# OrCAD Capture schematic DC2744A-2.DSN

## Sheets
1 PAGE2: size Custom; company: ANALOG DEVICES; note: DEMO BOARD BILL OF MATERIALS; note: HIGH OUTPUT VOLTAGE BOOST CONVERTER
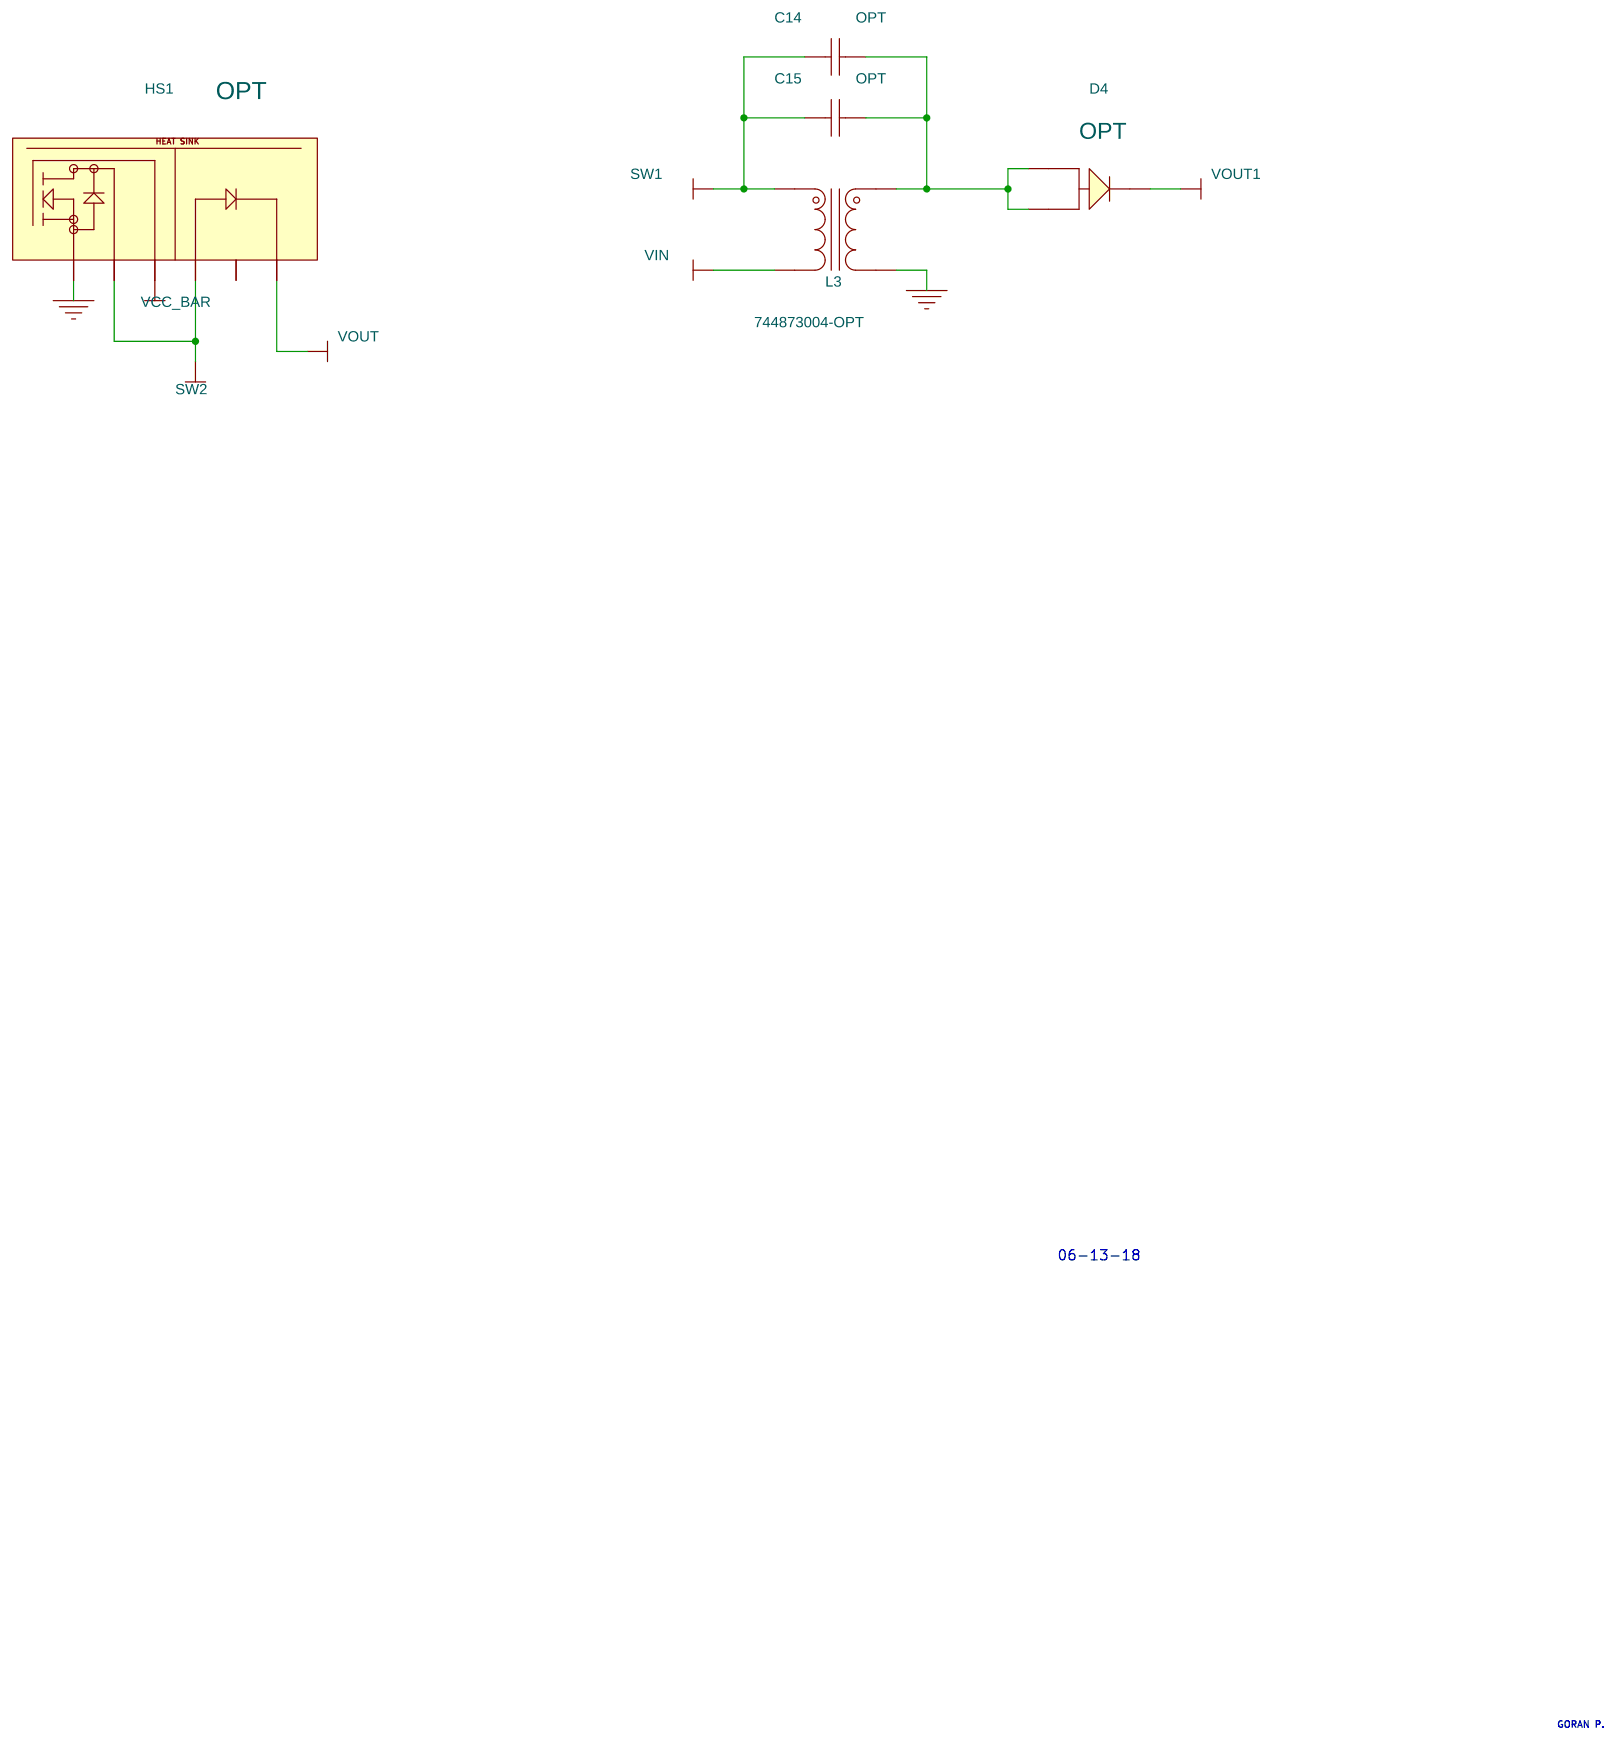
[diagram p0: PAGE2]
2 PAGE1: size Custom
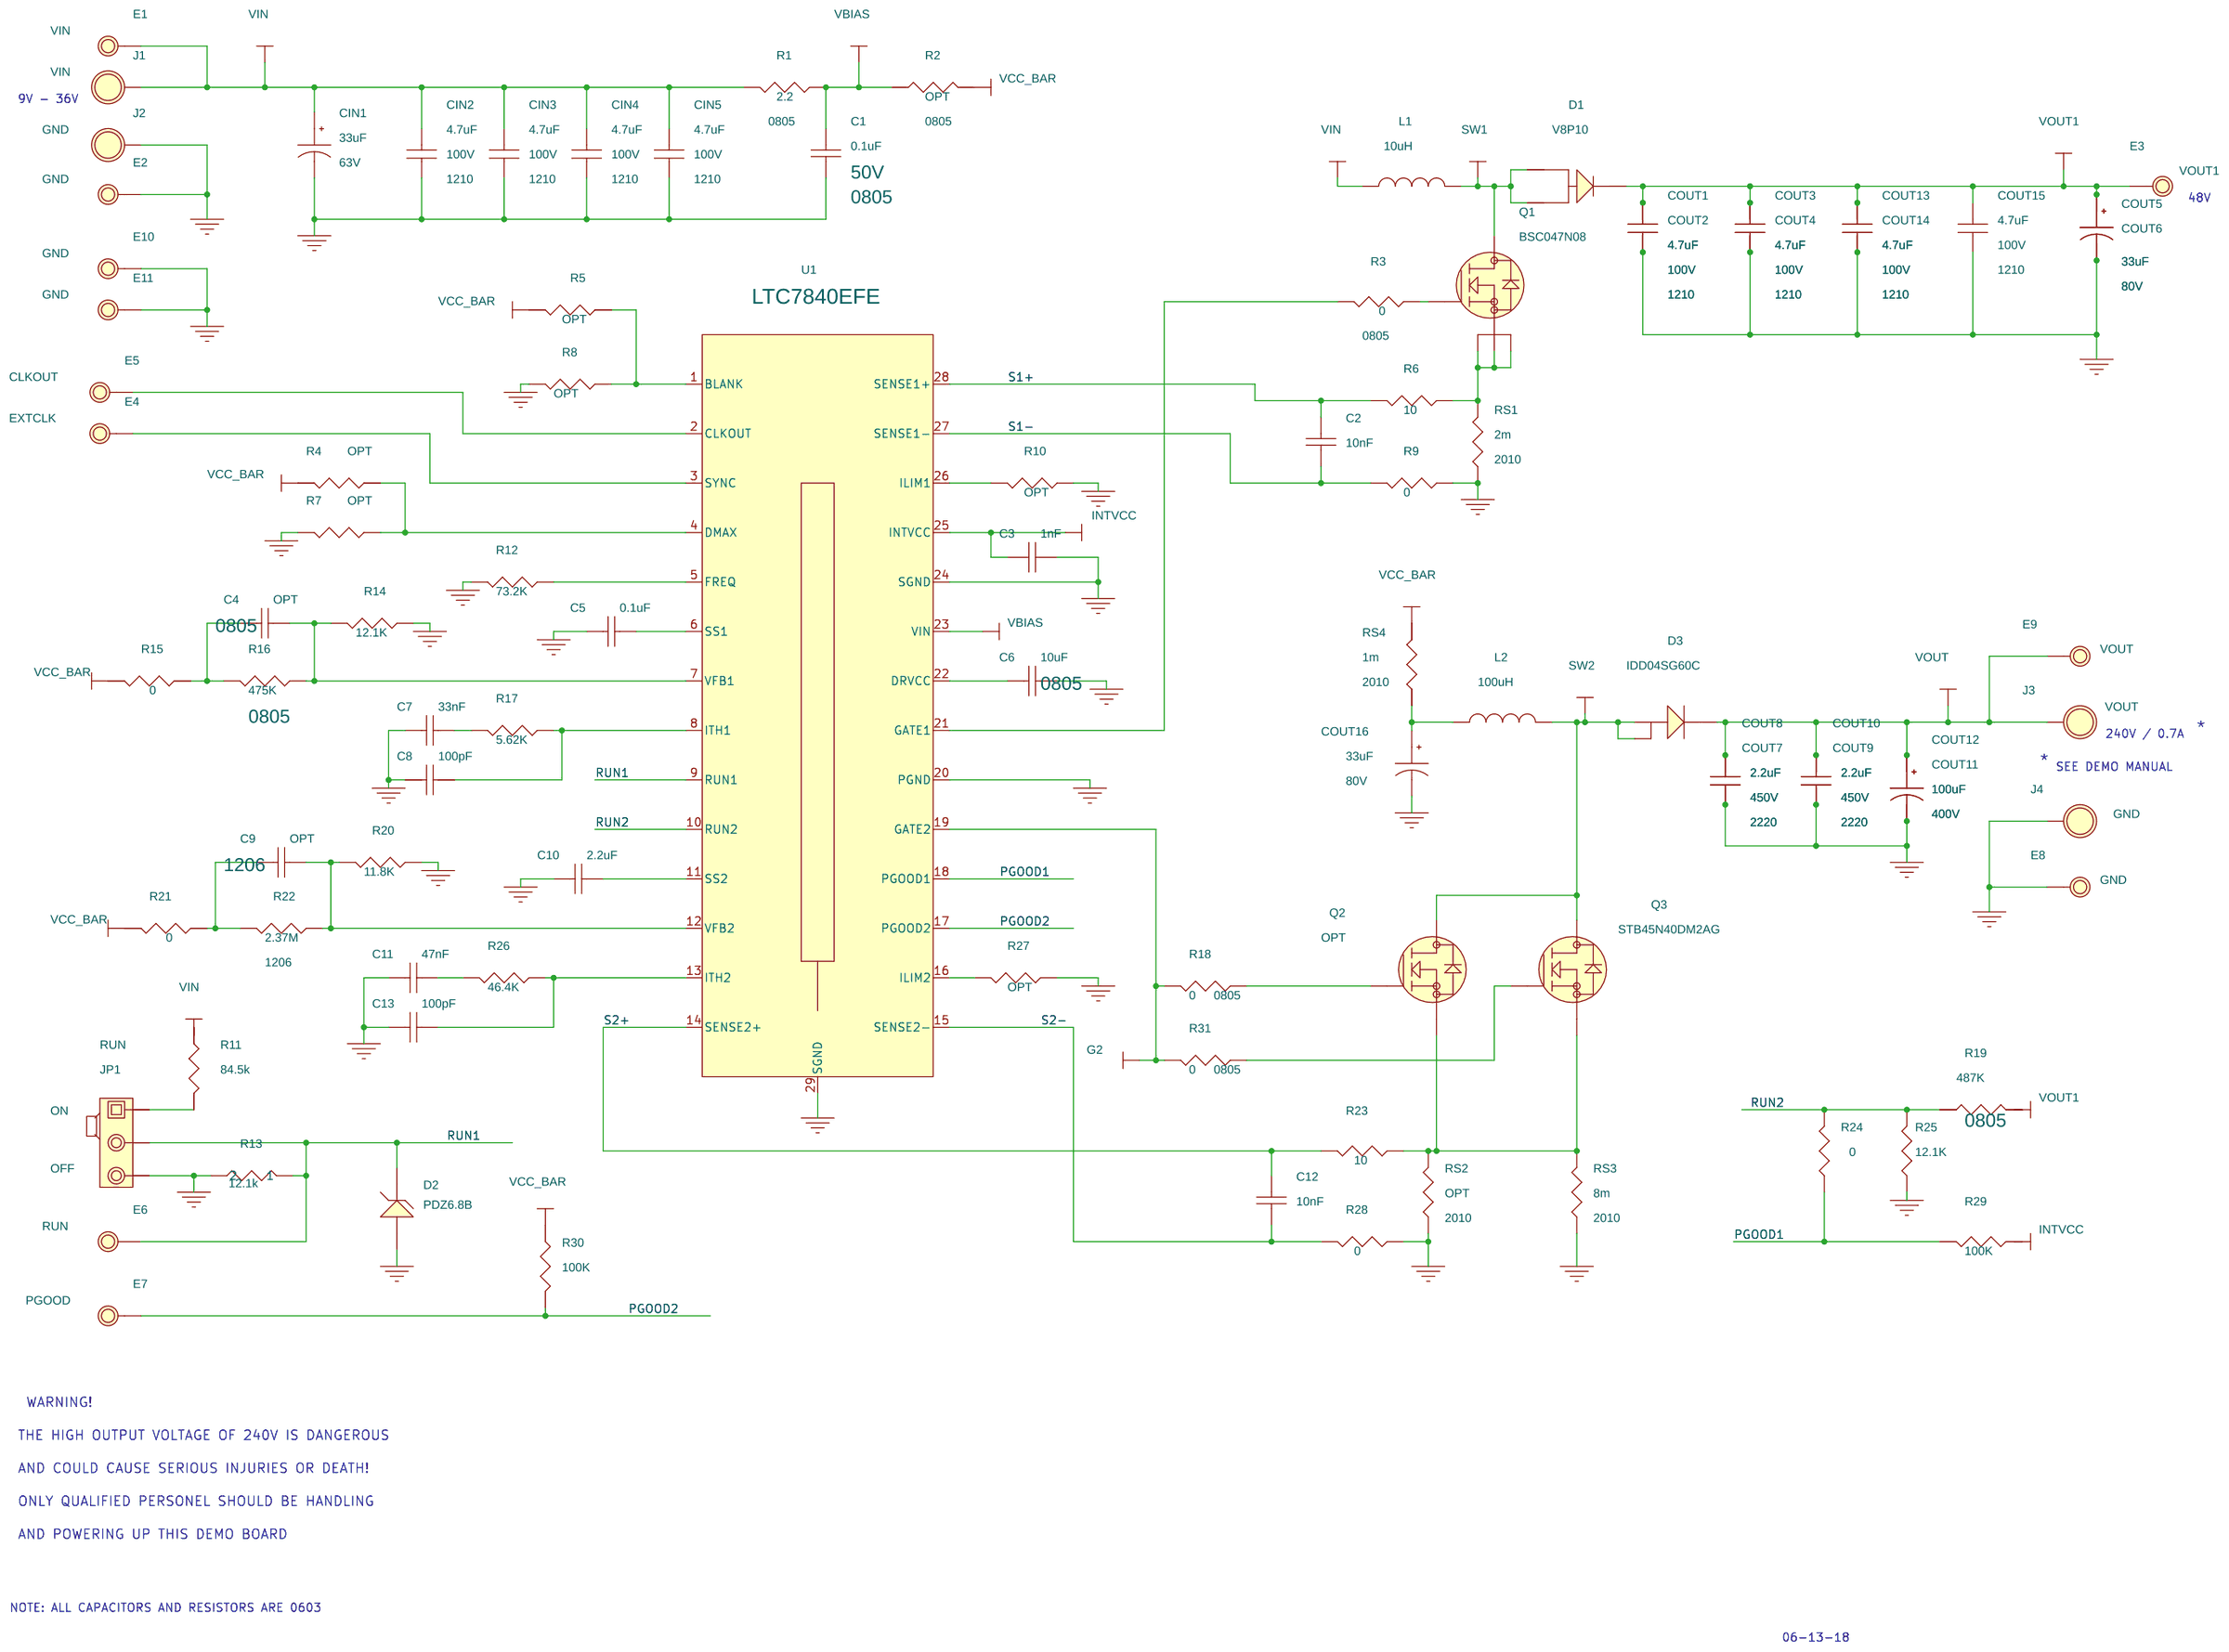
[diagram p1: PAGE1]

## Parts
sheet PAGE1
C1  0.1uF  [0805]
C2  10nF  [0603]
C3  1nF  [0603]
C4  OPT  [0805]
C5  0.1uF  [0603]
C6  10uF  [0805]
C7  33nF  [0603]
C8  100pF  [0603]
C9  OPT  [1206]
C10  2.2uF  [0603]
C11  47nF  [0603]
C12  10nF  [0603]
C13  100pF  [0603]
CIN1  33uF  [CAP-8.0]
CIN2  4.7uF  [1210]
CIN3  4.7uF  [1210]
CIN4  4.7uF  [1210]
CIN5  4.7uF  [1210]
COUT1  4.7uF  [1210]
COUT2  4.7uF  [1210]
COUT3  4.7uF  [1210]
COUT4  4.7uF  [1210]
COUT5  33uF  [CAP-10]
COUT6  33uF  [CAP-10]
COUT7  2.2uF  [2220]
COUT8  2.2uF  [2220]
COUT9  2.2uF  [2220]
COUT10  2.2uF  [2220]
COUT11  100uF  [CAP-TH-25X25]
COUT12  100uF  [CAP-TH-25X25]
COUT13  4.7uF  [1210]
COUT14  4.7uF  [1210]
COUT15  4.7uF  [1210]
COUT16  33uF  [CAP-10]
D1  60V/3Amp  [TO-277A]
D2  PDZ6.8B  [SOD-323]
D3  IDD04SG60C  [TO-252]
E1  Testpoint  [MM/2501]
E2  Testpoint  [MM/2501]
E3  Testpoint  [MM/2501]
E4  Testpoint  [MM/2501]
E5  Testpoint  [MM/2501]
E6  Testpoint  [MM/2501]
E7  Testpoint  [MM/2501]
E8  Testpoint  [MM/2501]
E9  Testpoint  [MM/2501]
E10  Testpoint  [MM/2501]
E11  Testpoint  [MM/2501]
J1  CON\LUG\10  [CON\LUG\10]
J2  CON\LUG\10  [CON\LUG\10]
J3  BANANA SMALL  [key-575-4]
J4  BANANA SMALL  [key-575-4]
JP1  3 Pins 2mm Ctrs.  [SIP\3P\2MM]
L1  10uH  [ser2900]
L2  100uH  [PCV-2-104-05L]
Q1  BSC047N08  [LFPAK]
Q2  OPT  [TO-263AB]
Q3  STB45N40DM2AG  [TO-263AB]
R1  2.2  [0805]
R2  OPT  [0805]
R3  0  [0805]
R4  OPT  [0603]
R5  OPT  [0603]
R6  10  [0603]
R7  OPT  [0603]
R8  OPT  [0603]
R9  0  [0603]
R10  OPT  [0603]
R11  84.5k  [0603]
R12  73.2K  [0603]
R13  12.1k  [0603]
R14  12.1K  [0603]
R15  0  [0603]
R16  475K  [0805]
R17  5.62K  [0603]
R18  0  [0805]
R19  487K  [0805]
R20  11.8K  [0603]
R21  0  [0603]
R22  2.37M  [1206]
R23  10  [0603]
R24  0  [0603]
R25  12.1K  [0603]
R26  46.4K  [0603]
R27  OPT  [0603]
R28  0  [0603]
R29  100K  [0603]
R30  100K  [0603]
R31  0  [0805]
RS1  2m  [2010]
RS2  OPT  [2010]
RS3  8m  [2010]
RS4  1m  [2010]
U1  LTC7840EFE  [TSSOP28EFE]
XJP1  2mm Ctrs.
sheet PAGE2
C14  OPT  [1812]
C15  OPT  [1812]
D4  OPT  [TO-277A]
HS1  OPT  [578622B03200G]
L3  744873004-OPT  [IND-74487]

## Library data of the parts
C1 = C2012X5R1A106M: 1st Part Field: 6.3V; VOLTAGE: 50V
C2-C15 = C2012X5R1A106M: 1st Part Field: 6.3V
CIN1 = 16SVP180MX_0_5: 1st Part Field: 63V; VOLTAGE: 63V
CIN2-CIN5 COUT1-COUT4 COUT13-COUT15 = JMK325BJ476MM-T: 1st Part Field: 50V; VOLTAGE: 100V
COUT5 = 16SVP180MX_0: 1st Part Field: 63V; VOLTAGE: 80V
COUT6 = 16SVP180MX_0_2: 1st Part Field: 63V; VOLTAGE: 80V
COUT7-COUT10 = JMK325BJ476MM-T: 1st Part Field: 50V; VOLTAGE: 450V
COUT11 = 16SVP180MX_0_3: 1st Part Field: 63V; VOLTAGE: 400V
COUT12 = 16SVP180MX_0_4: 1st Part Field: 63V; VOLTAGE: 400V
COUT16 = 16SVP180MX_0_1: 1st Part Field: 63V; VOLTAGE: 80V
D1 = PDS760_2: 5th Part Field: V8P10
D2 = DIODE_ZENER1_1: 9.1V: 10V
D3 = DIODE-POWERDI5_0
E1 = MillMax-2501-2: 9th Part Field: VIN
E2 E8 E10 E11 = MillMax-2501-2: 9th Part Field: GND
E3 = MillMax-2501-2: 9th Part Field: VOUT1
E4 = MillMax-2501-2: 9th Part Field: EXTCLK
E5 = MillMax-2501-2: 9th Part Field: CLKOUT
E6 = MillMax-2501-2: 9th Part Field: RUN
E7 = MillMax-2501-2: 9th Part Field: PGOOD
E9 = MillMax-2501-2: 9th Part Field: VOUT
J1 = BANANA_SMALL_1: Component: conn; Label: VIN
J2 J4 = BANANA_SMALL_1: Component: conn; Label: GND
J3 = BANANA_SMALL_1: Component: conn; Label: VOUT
JP1 = Samtec_TMM-103-02-L-S: HEADER, 3PIN, 2mm; 11th Part Field: OFF; 12th Part Field: RUN; 9th Part Field: ON; Part Number: SULLINS, NRPN031PAEN-RC
L1 L2 = IND: COMPFIXED: PA0515.471NLT
Q1 = MOSFET_N-DIODE-A-LFPAK_2
Q2 Q3 = MOSFET_N-DIODE-A-TO220
R1-R10 R12 R14-R31 RS1-RS4 = CR16-100JM_0
R11 = AAC-0402: RES, 0603 383k OHMS 1% 1/10W; 4TH PART FIELD: AAC,; Part Number: VISHAY CRCW0603383KFKEA; Tolerance: 1%
R13 = R: RES, 0603 121k OHMS 1% 1/10W; 5%: 1%; Part Number: VISHAY CRCW0603121KFKEA; Tol: 1%
U1 = LTC7840EFE_3
XJP1 = CommconCCIJ2MM-138G
D4 = PDS760_2
HS1 = HEAT_SINK_3: COMPFIXED: RJK0651DPB
L3 = IND-WU-744823220_0

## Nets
GND: C1.1 C3.1 C5.2 C6.1 C7.2 C8.2 C10.2 C11.2 C13.2 CIN1.2 CIN2.1 CIN3.1 CIN4.1 CIN5.1 COUT1.1 COUT2.1 COUT3.1 COUT4.1 COUT5.2 COUT6.2 COUT7.1 COUT8.1 COUT9.1 COUT10.1 COUT11.2 COUT12.2 COUT13.1 COUT14.1 COUT15.1 COUT16.2 D2.2 E2.1 E8.1 E10.1 E11.1 HS1.1 J2.1(TP) J4.1(TP) JP1.3 L3.3 R7.2 R8.2 R9.1 R10.1 R12.2 R13.2 R14.1 R20.1 R25.2 R27.1 R28.1 RS1.1 RS2.1 RS3.1 U1.20(PGND) U1.24(SGND) U1.29(SGND)
VIN: CIN1.1 CIN2.2 CIN3.2 CIN4.2 CIN5.2 E1.1 J1.1(TP) L1.1 L3.4 R1.2 R11.1
G2: HS1.3 R18.2 R31.2 U1.19(GATE2)
INTVCC: C3.2 R4.2 R5.2 R29.1 R30.1 U1.25(INTVCC)
PGOOD1: R24.2 R29.2 U1.18(PGOOD1)
PGOOD2: E7.1 R30.2 U1.17(PGOOD2)
RUN1: D2.1 E6.1 JP1.2 R13.1 U1.9(RUN1)
RUN2: R19.2 R24.1 R25.1 U1.10(RUN2)
S1+: C2.2 R6.2 U1.28(SENSE1+)
S1-: C2.1 R9.2 U1.27(SENSE1-)
S2+: C12.2 R23.2 U1.14(SENSE2+)
S2-: C12.1 R28.2 U1.15(SENSE2-)
SW1: C14.2 C15.2 D1.1 D1.2 L1.2 L3.1 Q1.5
SW2: D3.1 D3.3 HS1.2 HS1.4 L2.2 Q2.2 Q3.2
VBIAS: C1.2 R1.1 R2.1 U1.23(VIN)
VOUT: COUT7.2 COUT8.2 COUT9.2 COUT10.2 COUT11.1 COUT12.1 D3.2 E9.1 HS1.6 J3.1(TP) R21.2
VOUT1: COUT1.2 COUT2.2 COUT3.2 COUT4.2 COUT5.1 COUT6.1 COUT13.2 COUT14.2 COUT15.2 D1.3 D4.3 E3.1 R2.2 R15.2 R19.1 RS4.2
N19099559: Q2.3 Q3.3 R23.1 RS2.2 RS3.2
N19099563: Q3.1 R31.1
N19099757: Q2.1 R18.1
N19099891: Q1.1 Q1.2 Q1.3 R6.1 RS1.2
N19100112: Q1.4 R3.1
N19100135: R3.2 U1.21(GATE1)
N19100593: C10.1 U1.11(SS2)
N19100597: C13.1 R26.1 U1.13(ITH2)
N19101685: C9.1 R20.2 R22.1 U1.12(VFB2)
N19101696: C9.2 R21.1 R22.2
N19101753: C11.1 R26.2
N19101976: C5.1 U1.6(SS1)
N19101995: C7.1 R17.2
N19102016: C8.1 R17.1 U1.8(ITH1)
N19102170: R5.1 R8.1 U1.1(BLANK)
N19102204: R4.1 R7.1 U1.4(DMAX)
N19102362: E5.1 U1.2(CLKOUT)
N19102372: E4.1 U1.3(SYNC)
N19102561: C4.1 R14.2 R16.1 U1.7(VFB1)
N19102588: C4.2 R15.1 R16.2
N19102784: JP1.1 R11.2
N19104719: R12.1 U1.5(FREQ)
N19140898: R10.2 U1.26(ILIM1)
N19141372: R27.2 U1.16(ILIM2)
N19169414: C6.2 U1.22(DRVCC)
N19177529: COUT16.1 L2.1 RS4.1
N19179514: C14.1 C15.1 D4.1 D4.2 L3.2

Not connected (* = marked no-connect by the designer): HS1 5

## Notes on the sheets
sheet 1
- 06-13-18
- GORAN P.
sheet 2
- 9V - 36V
- 48V
- *
- 240V / 0.7A
- *
- SEE DEMO MANUAL
- WARNING!
- THE HIGH OUTPUT VOLTAGE OF 240V IS DANGEROUS
- AND COULD CAUSE SERIOUS INJURIES OR DEATH!
- ONLY QUALIFIED PERSONEL SHOULD BE HANDLING
- AND POWERING UP THIS DEMO BOARD
- NOTE: ALL CAPACITORS AND RESISTORS ARE 0603
- 06-13-18
